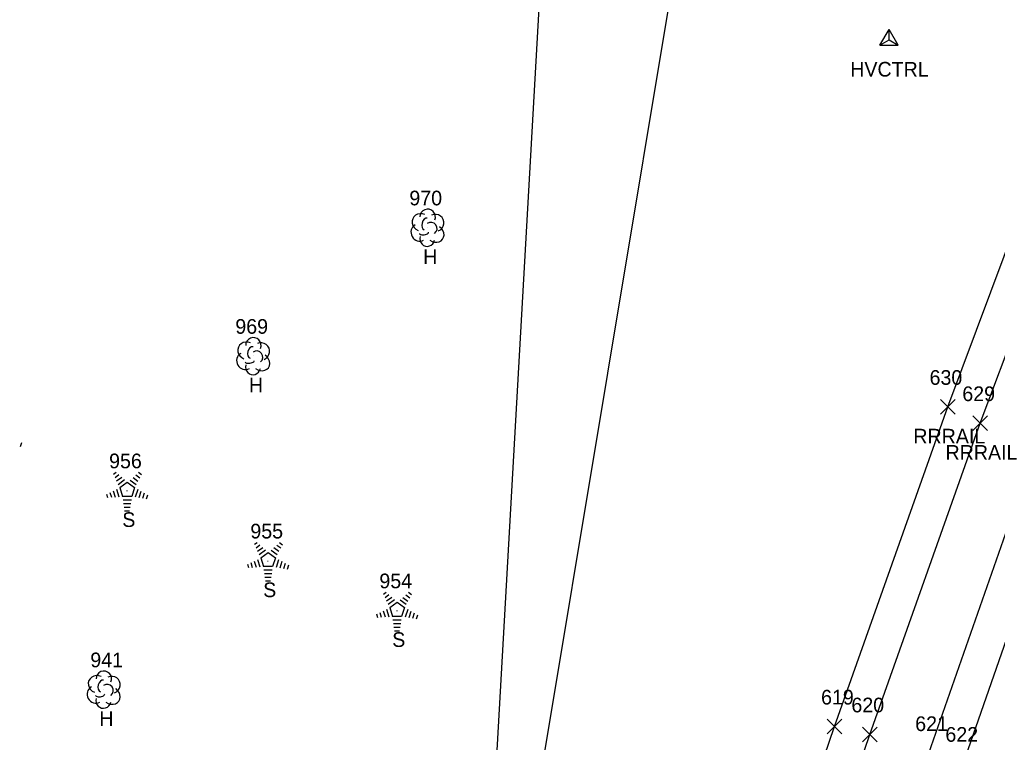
# Model space of a CAD drawing. Extents: x 1767353 to 1772625, y 740790 to 747702.
# Drawn here: x 1770199.3 to 1770332.7, y 742315.8 to 742414.3 of the extents above; entities that cross this region are included whole.
import ezdxf

# ---------------------------------------------------------------- set-up
doc = ezdxf.new("R2010")
doc.units = 0
for name, color, linetype in [('C_A', 7, 'Continuous'), ('CPSM', 7, 'Continuous'), ('L_A', 7, 'Continuous'), ('L_I', 7, 'Continuous'), ('LELB', 7, 'Continuous'), ('LTC', 7, 'Continuous'), ('LTD', 7, 'Continuous'), ('R_A', 7, 'Continuous'), ('R_I', 7, 'Continuous'), ('R_TIC', 7, 'Continuous'), ('RR', 7, 'Continuous')]:
    doc.layers.add(name, color=color, linetype=linetype)

msp = doc.modelspace()

# ---------------------------------------------------------------- linework, layer by layer
at = {"layer": 'CPSM'}
for p, q in [((1770316.69, 742410.84), (1770317.94, 742413)), ((1770316.69, 742410.84), (1770317.94, 742413)), ((1770316.69, 742410.84), (1770317.94, 742413)), ((1770316.69, 742410.84), (1770317.94, 742413)), ((1770316.69, 742410.84), (1770317.94, 742413)), ((1770316.69, 742410.84), (1770317.94, 742413)), ((1770316.69, 742410.84), (1770317.94, 742413)), ((1770316.69, 742410.84), (1770317.94, 742413)), ((1770316.69, 742410.84), (1770317.94, 742413)), ((1770316.69, 742410.84), (1770317.94, 742413)), ((1770316.69, 742410.84), (1770317.94, 742413)), ((1770316.69, 742410.84), (1770317.94, 742413)), ((1770316.69, 742410.84), (1770317.94, 742413)), ((1770316.69, 742410.84), (1770317.94, 742413)), ((1770316.69, 742410.84), (1770317.94, 742413)), ((1770319.19, 742410.84), (1770317.94, 742413)), ((1770317.95, 742411.56), (1770317.94, 742413)), ((1770319.19, 742410.84), (1770317.94, 742413)), ((1770317.95, 742411.56), (1770317.94, 742413)), ((1770319.19, 742410.84), (1770317.94, 742413)), ((1770317.95, 742411.56), (1770317.94, 742413)), ((1770319.19, 742410.84), (1770317.94, 742413)), ((1770317.95, 742411.56), (1770317.94, 742413)), ((1770319.19, 742410.84), (1770317.94, 742413)), ((1770317.95, 742411.56), (1770317.94, 742413)), ((1770319.19, 742410.84), (1770317.94, 742413)), ((1770317.95, 742411.56), (1770317.94, 742413)), ((1770319.19, 742410.84), (1770317.94, 742413)), ((1770317.95, 742411.56), (1770317.94, 742413)), ((1770319.19, 742410.84), (1770317.94, 742413)), ((1770317.95, 742411.56), (1770317.94, 742413)), ((1770319.19, 742410.84), (1770317.94, 742413)), ((1770317.95, 742411.56), (1770317.94, 742413)), ((1770319.19, 742410.84), (1770317.94, 742413)), ((1770317.95, 742411.56), (1770317.94, 742413)), ((1770319.19, 742410.84), (1770317.94, 742413)), ((1770317.95, 742411.56), (1770317.94, 742413)), ((1770319.19, 742410.84), (1770317.94, 742413)), ((1770317.95, 742411.56), (1770317.94, 742413)), ((1770319.19, 742410.84), (1770317.94, 742413)), ((1770317.95, 742411.56), (1770317.94, 742413)), ((1770319.19, 742410.84), (1770317.94, 742413)), ((1770317.95, 742411.56), (1770317.94, 742413)), ((1770319.19, 742410.84), (1770317.94, 742413)), ((1770317.95, 742411.56), (1770317.94, 742413)), ((1770316.69, 742410.84), (1770317.95, 742411.56)), ((1770316.69, 742410.84), (1770317.95, 742411.56)), ((1770316.69, 742410.84), (1770317.95, 742411.56)), ((1770316.69, 742410.84), (1770317.95, 742411.56)), ((1770316.69, 742410.84), (1770317.95, 742411.56)), ((1770316.69, 742410.84), (1770317.95, 742411.56)), ((1770316.69, 742410.84), (1770317.95, 742411.56)), ((1770316.69, 742410.84), (1770317.95, 742411.56)), ((1770316.69, 742410.84), (1770317.95, 742411.56)), ((1770316.69, 742410.84), (1770317.95, 742411.56)), ((1770316.69, 742410.84), (1770317.95, 742411.56)), ((1770316.69, 742410.84), (1770317.95, 742411.56)), ((1770316.69, 742410.84), (1770317.95, 742411.56)), ((1770316.69, 742410.84), (1770317.95, 742411.56)), ((1770316.69, 742410.84), (1770317.95, 742411.56)), ((1770316.69, 742410.84), (1770319.19, 742410.84)), ((1770316.69, 742410.84), (1770319.19, 742410.84)), ((1770316.69, 742410.84), (1770319.19, 742410.84)), ((1770316.69, 742410.84), (1770319.19, 742410.84)), ((1770316.69, 742410.84), (1770319.19, 742410.84)), ((1770316.69, 742410.84), (1770319.19, 742410.84)), ((1770316.69, 742410.84), (1770319.19, 742410.84)), ((1770316.69, 742410.84), (1770319.19, 742410.84)), ((1770316.69, 742410.84), (1770319.19, 742410.84)), ((1770316.69, 742410.84), (1770319.19, 742410.84)), ((1770316.69, 742410.84), (1770319.19, 742410.84)), ((1770316.69, 742410.84), (1770319.19, 742410.84)), ((1770316.69, 742410.84), (1770319.19, 742410.84)), ((1770316.69, 742410.84), (1770319.19, 742410.84)), ((1770316.69, 742410.84), (1770319.19, 742410.84)), ((1770317.95, 742411.56), (1770317.95, 742411.56)), ((1770317.95, 742411.56), (1770319.19, 742410.84)), ((1770317.95, 742411.56), (1770317.95, 742411.56)), ((1770317.95, 742411.56), (1770319.19, 742410.84)), ((1770317.95, 742411.56), (1770317.95, 742411.56)), ((1770317.95, 742411.56), (1770319.19, 742410.84)), ((1770317.95, 742411.56), (1770317.95, 742411.56)), ((1770317.95, 742411.56), (1770319.19, 742410.84)), ((1770317.95, 742411.56), (1770317.95, 742411.56)), ((1770317.95, 742411.56), (1770319.19, 742410.84)), ((1770317.95, 742411.56), (1770317.95, 742411.56)), ((1770317.95, 742411.56), (1770319.19, 742410.84)), ((1770317.95, 742411.56), (1770317.95, 742411.56)), ((1770317.95, 742411.56), (1770319.19, 742410.84)), ((1770317.95, 742411.56), (1770317.95, 742411.56)), ((1770317.95, 742411.56), (1770319.19, 742410.84)), ((1770317.95, 742411.56), (1770317.95, 742411.56)), ((1770317.95, 742411.56), (1770319.19, 742410.84)), ((1770317.95, 742411.56), (1770317.95, 742411.56)), ((1770317.95, 742411.56), (1770319.19, 742410.84)), ((1770317.95, 742411.56), (1770317.95, 742411.56)), ((1770317.95, 742411.56), (1770319.19, 742410.84)), ((1770317.95, 742411.56), (1770317.95, 742411.56)), ((1770317.95, 742411.56), (1770319.19, 742410.84)), ((1770317.95, 742411.56), (1770317.95, 742411.56)), ((1770317.95, 742411.56), (1770319.19, 742410.84)), ((1770317.95, 742411.56), (1770317.95, 742411.56)), ((1770317.95, 742411.56), (1770319.19, 742410.84)), ((1770317.95, 742411.56), (1770317.95, 742411.56)), ((1770317.95, 742411.56), (1770319.19, 742410.84))]:
    msp.add_line(p, q, dxfattribs=at)
at = {"layer": 'LELB'}
for points in [[(1770162.33, 742204.96), (1770182.69, 742228.32), (1770195.35, 742241.18), (1770232.57, 742237.56), (1770259.25, 742271.37), (1770269.87, 742307.96), (1770289.26, 742424.34), (1770288.5, 742547.79), (1770295.74, 742644.73), (1770282.22, 742645.21)], [(1770251.29, 742275.75), (1770264.27, 742310.68), (1770270.74, 742425.56), (1770277.6, 742545.58), (1770282.22, 742645.21)]]:
    msp.add_lwpolyline(points, dxfattribs=at)
at = {"layer": 'LTC'}
for p, q in [((1770199.61, 742356.63), (1770199.42, 742356.06)), ((1770212.15, 742352.36), (1770212.5, 742352.61)), ((1770212.36, 742351.89), (1770212.89, 742352.28)), ((1770212.57, 742351.43), (1770213.27, 742351.94)), ((1770214.81, 742351.9), (1770215.48, 742351.41)), ((1770215.18, 742352.25), (1770215.73, 742351.85)), ((1770215.55, 742352.6), (1770215.97, 742352.29)), ((1770212.78, 742350.96), (1770213.66, 742351.6)), ((1770213, 742350.51), (1770214.01, 742351.24)), ((1770213, 742350.51), (1770213.39, 742349.31)), ((1770214.01, 742351.24), (1770215.01, 742350.51)), ((1770214.43, 742351.55), (1770215.24, 742350.96)), ((1770215.01, 742350.51), (1770214.62, 742349.31)), ((1770211.18, 742349.64), (1770211.33, 742349.17)), ((1770211.64, 742349.85), (1770211.85, 742349.2)), ((1770212.09, 742350.07), (1770212.36, 742349.23)), ((1770212.55, 742350.29), (1770212.88, 742349.27)), ((1770214.62, 742349.31), (1770213.39, 742349.31)), ((1770215.45, 742350.24), (1770215.11, 742349.2)), ((1770215.89, 742349.99), (1770215.61, 742349.11)), ((1770216.34, 742349.74), (1770216.1, 742349.01)), ((1770216.78, 742349.49), (1770216.6, 742348.92)), ((1770214.58, 742348.81), (1770213.44, 742348.81)), ((1770214.5, 742348.31), (1770213.51, 742348.31)), ((1770214.41, 742347.81), (1770213.58, 742347.81)), ((1770214.33, 742347.31), (1770213.66, 742347.31)), ((1770231.37, 742342.79), (1770231.73, 742343.04)), ((1770231.58, 742342.32), (1770232.11, 742342.71)), ((1770234.4, 742342.68), (1770234.95, 742342.28)), ((1770234.77, 742343.03), (1770235.19, 742342.72)), ((1770231.79, 742341.86), (1770232.49, 742342.37)), ((1770232, 742341.39), (1770232.88, 742342.03)), ((1770232.22, 742340.93), (1770233.24, 742341.67)), ((1770233.24, 742341.67), (1770234.23, 742340.94)), ((1770233.66, 742341.98), (1770234.47, 742341.39)), ((1770234.03, 742342.33), (1770234.71, 742341.84)), ((1770230.4, 742340.07), (1770230.56, 742339.6)), ((1770230.86, 742340.28), (1770231.07, 742339.63)), ((1770231.31, 742340.5), (1770231.59, 742339.66)), ((1770231.77, 742340.72), (1770232.1, 742339.7)), ((1770232.22, 742340.93), (1770232.61, 742339.74)), ((1770234.23, 742340.94), (1770233.84, 742339.74)), ((1770234.67, 742340.67), (1770234.33, 742339.63)), ((1770235.12, 742340.42), (1770234.83, 742339.54)), ((1770235.56, 742340.17), (1770235.32, 742339.44)), ((1770236, 742339.92), (1770235.82, 742339.35)), ((1770233.84, 742339.74), (1770232.61, 742339.74)), ((1770233.8, 742339.24), (1770232.66, 742339.24)), ((1770233.72, 742338.74), (1770232.73, 742338.74)), ((1770233.64, 742338.24), (1770232.8, 742338.24)), ((1770233.55, 742337.74), (1770232.88, 742337.74)), ((1770248.97, 742336), (1770249.32, 742336.26)), ((1770249.18, 742335.53), (1770249.71, 742335.92)), ((1770252, 742335.89), (1770252.55, 742335.49)), ((1770252.37, 742336.24), (1770252.79, 742335.94)), ((1770249.39, 742335.07), (1770250.09, 742335.58)), ((1770249.6, 742334.6), (1770250.48, 742335.24)), ((1770249.82, 742334.15), (1770250.84, 742334.88)), ((1770250.84, 742334.88), (1770251.83, 742334.16)), ((1770251.26, 742335.2), (1770252.06, 742334.61)), ((1770251.63, 742335.54), (1770252.31, 742335.05)), ((1770248, 742333.28), (1770248.16, 742332.81)), ((1770248.46, 742333.5), (1770248.67, 742332.84)), ((1770248.91, 742333.71), (1770249.18, 742332.88)), ((1770249.37, 742333.93), (1770249.7, 742332.91)), ((1770249.82, 742334.15), (1770250.21, 742332.95)), ((1770251.83, 742334.16), (1770251.44, 742332.95)), ((1770252.27, 742333.89), (1770251.93, 742332.85)), ((1770252.71, 742333.64), (1770252.43, 742332.75)), ((1770253.16, 742333.39), (1770252.92, 742332.66)), ((1770253.6, 742333.14), (1770253.42, 742332.56)), ((1770251.44, 742332.95), (1770250.21, 742332.95)), ((1770251.4, 742332.45), (1770250.26, 742332.45)), ((1770251.32, 742331.95), (1770250.33, 742331.95)), ((1770251.24, 742331.45), (1770250.4, 742331.45)), ((1770251.15, 742330.95), (1770250.48, 742330.95))]:
    msp.add_line(p, q, dxfattribs=at)
at = {"layer": 'LTD'}
for p, q in [((1770254.95, 742386), (1770254.95, 742386)), ((1770254.95, 742386), (1770254.95, 742386)), ((1770231.18, 742368.49), (1770231.18, 742368.49)), ((1770231.18, 742368.49), (1770231.18, 742368.49)), ((1770210.78, 742323.02), (1770210.78, 742323.02)), ((1770210.78, 742323.02), (1770210.78, 742323.02))]:
    msp.add_line(p, q, dxfattribs=at)
for centre in [(1770255, 742387.44), (1770231.22, 742369.92), (1770210.83, 742324.45)]:
    msp.add_arc(centre, 1.05, 335.5272, 180.9563, dxfattribs=at)
for centre, major_axis, ratio, start_param, end_param in [((1770254.16, 742386.67), (1.21, -0.51), 0.895232, 1.570796, 4.712389), ((1770255.99, 742386.59), (-1.14, -0.48), 0.949671, 1.570796, 4.712389), ((1770254.74, 742386.46), (-0.208, -0.792), 0.645439, 3.141593, 6.283185), ((1770255.45, 742385.84), (-0.5, 0.667), 0.989748, 3.141593, 6.283185), ((1770253.87, 742385.3), (0.58, -1.04), 0.959034, 3.141593, 6.283185), ((1770254.49, 742385.25), (-0.625, -0.083), 0.423636, 0, 3.141593), ((1770255.95, 742385.17), (-1.09, 0.79), 0.841452, 1.570796, 4.712389), ((1770254.95, 742384.5), (0.26, 1.06), 0.942809, 1.570796, 4.712389), ((1770230.38, 742369.15), (1.21, -0.51), 0.895232, 1.570796, 4.712389), ((1770230.97, 742368.94), (-0.208, -0.792), 0.645439, 3.141593, 6.283185), ((1770231.68, 742368.32), (-0.5, 0.667), 0.989748, 3.141593, 6.283185), ((1770232.22, 742369.07), (-1.14, -0.48), 0.949671, 1.570796, 4.712389), ((1770230.09, 742367.78), (0.58, -1.04), 0.959034, 3.141593, 6.283185), ((1770230.72, 742367.74), (-0.625, -0.083), 0.423636, 0, 3.141593), ((1770232.18, 742367.65), (-1.09, 0.79), 0.841452, 1.570796, 4.712389), ((1770231.18, 742366.99), (0.26, 1.06), 0.942809, 1.570796, 4.712389), ((1770209.99, 742323.69), (1.21, -0.51), 0.895232, 1.570796, 4.712389), ((1770210.57, 742323.48), (-0.208, -0.792), 0.645439, 3.141593, 6.283185), ((1770211.28, 742322.85), (-0.5, 0.667), 0.989748, 3.141593, 6.283185), ((1770211.82, 742323.6), (-1.14, -0.48), 0.949671, 1.570796, 4.712389), ((1770209.7, 742322.31), (0.58, -1.04), 0.959034, 3.141593, 6.283185), ((1770211.78, 742322.19), (-1.09, 0.79), 0.841452, 1.570796, 4.712389), ((1770210.78, 742321.52), (0.26, 1.06), 0.942809, 1.570796, 4.712389), ((1770210.32, 742322.27), (-0.625, -0.083), 0.423636, 0, 3.141593)]:
    msp.add_ellipse(centre, major_axis=major_axis, ratio=ratio, start_param=start_param, end_param=end_param, dxfattribs=at)
at = {"layer": 'R_TIC'}
for points in [[(1770324.96, 742360.53), (1770326.96, 742362.53)], [(1770326.96, 742360.53), (1770324.96, 742362.53)], [(1770329.35, 742358.31), (1770331.35, 742360.31)], [(1770331.35, 742358.31), (1770329.35, 742360.31)], [(1770309.51, 742316.94), (1770311.51, 742318.94)], [(1770311.51, 742316.94), (1770309.51, 742318.94)], [(1770314.3, 742315.87), (1770316.3, 742317.87)], [(1770316.3, 742315.87), (1770314.3, 742317.87)]]:
    msp.add_lwpolyline(points, dxfattribs=at)
at = {"layer": 'RR'}
for points in [[(1770221.78, 741982.04), (1770226.9, 742005.14), (1770231.58, 742026.58), (1770238.97, 742057.62), (1770247.46, 742091.31), (1770255.17, 742120.86), (1770262.38, 742147.12), (1770270.79, 742177.04), (1770278.58, 742203.25), (1770285.57, 742226.22), (1770292.18, 742247.12), (1770303.7, 742282.6), (1770315.3, 742316.87), (1770330.35, 742359.31), (1770344.25, 742396.26), (1770362.68, 742444.08), (1770381.25, 742488.48), (1770399.89, 742531.75), (1770427.72, 742593.02), (1770459.92, 742661.06), (1770775.2, 743314.07), (1770996.39, 743772.66), (1771192.02, 744177.67), (1771329.71, 744462.72)], [(1770217.88, 741982.89), (1770224.63, 742006.05), (1770231.58, 742026.58), (1770242.49, 742057.3), (1770253.86, 742089.03), (1770263.22, 742117.76), (1770271, 742143.83), (1770279.57, 742174.49), (1770286.79, 742199.43), (1770293.9, 742223.08), (1770300.84, 742244.95), (1770311.67, 742279.15), (1770323.34, 742314.32), (1770337.98, 742356.11), (1770351.9, 742393.8), (1770370.52, 742441.44), (1770388.76, 742485.07), (1770407.79, 742528.71), (1770435.51, 742589.24), (1770468.44, 742657.89), (1770783.17, 743309.95), (1771004.51, 743768.91), (1771200.35, 744174.24), (1771337.45, 744458.43)], [(1770217.02, 741983.21), (1770222.11, 742006.18), (1770226.99, 742028.12), (1770234.33, 742059.23), (1770242.65, 742092.71), (1770250.33, 742121.94), (1770257.59, 742148.49), (1770265.95, 742178.19), (1770273.77, 742204.67), (1770280.68, 742227.53), (1770287.46, 742248.27), (1770299.11, 742284.6), (1770310.51, 742317.94), (1770325.96, 742361.53), (1770339.5, 742397.74), (1770358.03, 742445.88), (1770376.8, 742490.97), (1770395.2, 742533.35), (1770423.54, 742595.68), (1770455.2, 742662.62), (1770770.92, 743316.68), (1770991.9, 743774.87)], [(1770222.72, 741981.76), (1770229.32, 742004.36), (1770235.77, 742023.83), (1770247.09, 742055.41), (1770258.52, 742087.39), (1770268.11, 742116.55), (1770275.73, 742142.21), (1770291.55, 742198.01), (1770296.52, 742214.73), (1770305.48, 742243.41), (1770316.35, 742277.3), (1770328.03, 742312.86), (1770342.4, 742354.07), (1770356.59, 742392.13), (1770375.3, 742439.98), (1770392.87, 742482.18), (1770412.29, 742526.82), (1770439.88, 742586.94), (1770472.88, 742655.84), (1770787.34, 743307.49), (1771008.99, 743766.96)]]:
    msp.add_lwpolyline(points, dxfattribs=at)

# ---------------------------------------------------------------- texts
at = {"layer": 'C_A'}
msp.add_text('HVCTRL', height=2, dxfattribs=at).set_placement((1770312.64, 742406.56))
msp.add_text('HVCTRL', height=2, dxfattribs=at).set_placement((1770312.64, 742406.56))
msp.add_text('HVCTRL', height=2, dxfattribs=at).set_placement((1770312.64, 742406.56))
msp.add_text('HVCTRL', height=2, dxfattribs=at).set_placement((1770312.64, 742406.56))
msp.add_text('HVCTRL', height=2, dxfattribs=at).set_placement((1770312.64, 742406.56))
msp.add_text('HVCTRL', height=2, dxfattribs=at).set_placement((1770312.64, 742406.56))
msp.add_text('HVCTRL', height=2, dxfattribs=at).set_placement((1770312.64, 742406.56))
msp.add_text('HVCTRL', height=2, dxfattribs=at).set_placement((1770312.64, 742406.56))
msp.add_text('HVCTRL', height=2, dxfattribs=at).set_placement((1770312.64, 742406.56))
msp.add_text('HVCTRL', height=2, dxfattribs=at).set_placement((1770312.64, 742406.56))
msp.add_text('HVCTRL', height=2, dxfattribs=at).set_placement((1770312.64, 742406.56))
msp.add_text('HVCTRL', height=2, dxfattribs=at).set_placement((1770312.64, 742406.56))
msp.add_text('HVCTRL', height=2, dxfattribs=at).set_placement((1770312.64, 742406.56))
msp.add_text('HVCTRL', height=2, dxfattribs=at).set_placement((1770312.64, 742406.56))
msp.add_text('HVCTRL', height=2, dxfattribs=at).set_placement((1770312.64, 742406.56))
at = {"layer": 'L_A'}
for s, p in [('H', (1770254.38, 742381)), ('H', (1770230.61, 742363.49)), ('S', (1770213.34, 742345.15)), ('S', (1770232.56, 742335.58)), ('S', (1770250.16, 742328.79)), ('H', (1770210.21, 742318.02))]:
    msp.add_text(s, height=2, dxfattribs=at).set_placement(p)
at = {"layer": 'L_I'}
for s, p in [('970', (1770252.5, 742389)), ('969', (1770228.76, 742371.49)), ('956', (1770211.54, 742353.15)), ('955', (1770230.81, 742343.58)), ('954', (1770248.41, 742336.79)), ('941', (1770208.98, 742326.02))]:
    msp.add_text(s, height=2, dxfattribs=at).set_placement(p)
at = {"layer": 'LTC'}
for p in [(1770213.9, 742350.25), (1770233.12, 742340.68), (1770250.72, 742333.9)]:
    msp.add_text('.', height=1.04, rotation=270, dxfattribs=at).set_placement(p)
at = {"layer": 'R_A'}
for p in [(1770321.25, 742356.53), (1770325.64, 742354.31)]:
    msp.add_text('RRRAIL', height=2, dxfattribs=at).set_placement(p)
at = {"layer": 'R_I'}
for s, p in [('630', (1770323.46, 742364.53)), ('629', (1770327.93, 742362.31)), ('619', (1770308.66, 742320.94)), ('620', (1770312.8, 742319.87)), ('621', (1770321.5, 742317.32)), ('622', (1770325.62, 742315.86))]:
    msp.add_text(s, height=2, dxfattribs=at).set_placement(p)

doc.saveas('drawing.dxf')
